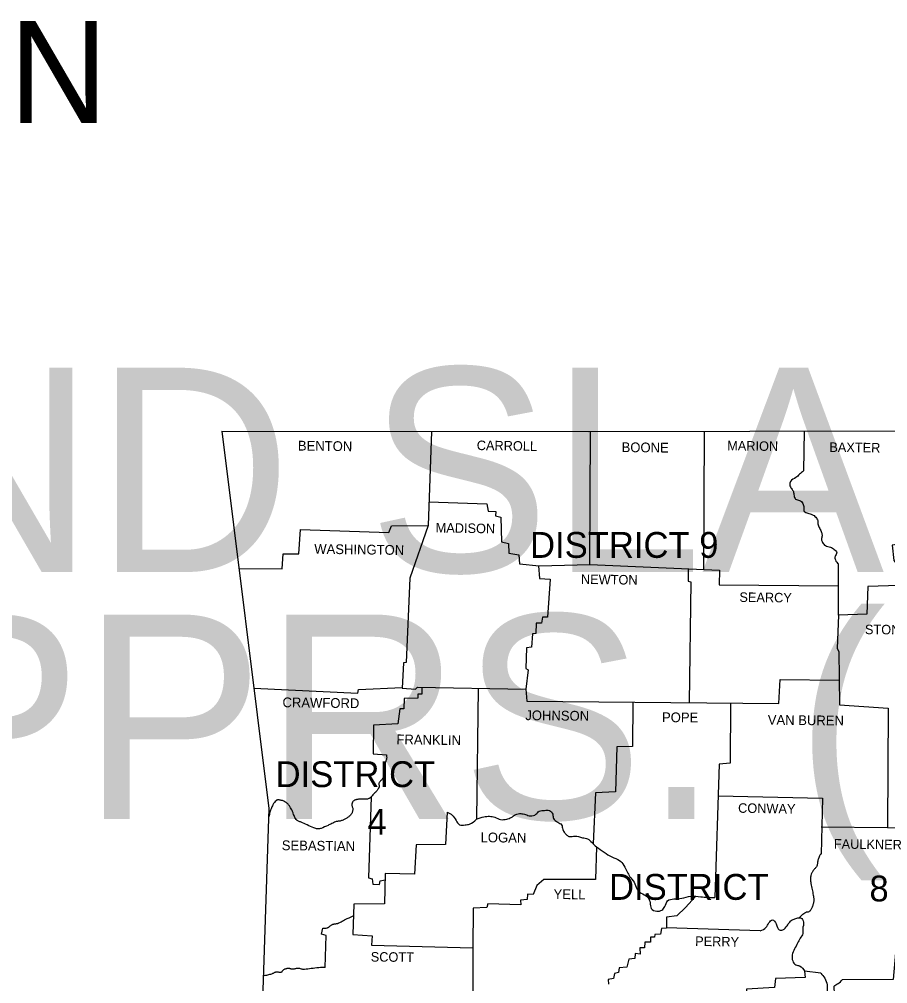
# Model space of a CAD drawing. Extents: x 982240 to 1103002, y 974866 to 1054902.
# Drawn here: x 1073786 to 1087558, y 1039317 to 1054617 of the extents above; entities that cross this region are included whole.
import ezdxf

# ---------------------------------------------------------------- set-up
doc = ezdxf.new("R2010")
doc.units = 0
for name, color, linetype in [('1', 7, 'Continuous'), ('Default', 7, 'Continuous'), ('R_Draft', 7, 'Continuous')]:
    doc.layers.add(name, color=color, linetype=linetype)

msp = doc.modelspace()

# ---------------------------------------------------------------- linework, layer by layer
at = {"layer": '1'}
for points in [[(1076997, 1048082), (1082818, 1048078), (1087927, 1048089), (1093953, 1048183), (1096746, 1048247)], [(1076997, 1048082), (1077743, 1042099), (1077419, 1032332)], [(1087927, 1048089), (1087934, 1047211), (1087873, 1047207), (1087883, 1046311), (1087631, 1046275), (1087653, 1046033), (1087739, 1045922), (1087732, 1045637), (1087243, 1045619), (1087225, 1045180), (1086778, 1045166), (1086757, 1044633), (1086782, 1044590), (1086793, 1043740), (1087563, 1043690), (1087552, 1041793), (1088164, 1041775), (1088164, 1039845), (1087682, 1039809), (1087646, 1039384), (1086836, 1039381)], [(1077269, 1045904), (1077955, 1045900), (1077973, 1046138), (1078221, 1046138), (1078243, 1046523), (1079647, 1046473), (1079690, 1046581), (1080270, 1046584), (1079978, 1045749), (1079920, 1044413), (1079877, 1044410), (1079856, 1044007), (1080068, 1043989), (1080100, 1044021), (1081818, 1043989), (1081836, 1043798)], [(1081836, 1043798), (1085832, 1043765), (1085850, 1044143), (1086788, 1044133)], [(1081062, 1044003), (1081036, 1041926)], [(1080572, 1042041), (1080547, 1041526), (1080079, 1041523), (1080054, 1041055), (1079589, 1041065), (1079575, 1040583), (1079089, 1040579), (1079075, 1040097), (1079380, 1040079), (1079370, 1039931), (1080980, 1039887)], [(1080980, 1039887), (1080975, 1038412), (1080795, 1038409), (1080810, 1038301), (1080637, 1038304), (1080633, 1038225), (1080464, 1038225), (1080468, 1038167), (1080216, 1038160), (1080212, 1037941), (1079967, 1037962), (1079928, 1036191), (1078542, 1036195), (1078509, 1035784), (1078560, 1035748), (1078556, 1035287), (1077518, 1035333)], [(1086498, 1039485), (1086238, 1039514), (1086249, 1039417), (1085778, 1039399), (1085763, 1039258), (1085320, 1039233), (1085295, 1038981), (1085360, 1038949), (1085360, 1038783)]]:
    msp.add_lwpolyline(points, dxfattribs=at)
for points in [[(1080572, 1042041), (1080651, 1041991), (1080712, 1041908), (1080766, 1041839), (1080856, 1041836), (1080928, 1041850), (1081036, 1041926)], [(1086498, 1039485), (1086559, 1039406), (1086595, 1039298), (1086595, 1039175), (1086624, 1039075), (1086681, 1039053), (1086717, 1039139), (1086710, 1039226), (1086710, 1039276), (1086771, 1039319), (1086836, 1039381)]]:
    msp.add_spline(points, degree=3, dxfattribs=at)
at = {"layer": 'Default'}
for points in [[(1080321, 1048080), (1080270, 1046584)], [(1080282, 1046960), (1081198, 1046930), (1081220, 1046815), (1081342, 1046811), (1081339, 1046739), (1081425, 1046717), (1081432, 1046325), (1081544, 1046300), (1081551, 1046145), (1081710, 1046123), (1081717, 1045979), (1082030, 1045947), (1082836, 1045965), (1082844, 1048078)], [(1084647, 1048082), (1084636, 1045889)], [(1086231, 1048085), (1086224, 1047452)], [(1082022, 1045948), (1082037, 1045745), (1082203, 1045735), (1082160, 1045130), (1082084, 1045133), (1082070, 1045036), (1081983, 1045036), (1081980, 1044871), (1081926, 1044867), (1081908, 1044655), (1081828, 1044644), (1081818, 1044320), (1081854, 1044295), (1081818, 1043989)], [(1082836, 1045965), (1084888, 1045879), (1084885, 1045645), (1086776, 1045630)], [(1084395, 1045899), (1084392, 1045702), (1084438, 1045691), (1084409, 1043777)], [(1086778, 1045166), (1086775, 1045976)], [(1077505, 1044004), (1079157, 1043927), (1079165, 1043985), (1079856, 1044018)], [(1080172, 1044020), (1080172, 1043909), (1080104, 1043909), (1080108, 1043845), (1079888, 1043841), (1079884, 1043679), (1079823, 1043679), (1079791, 1043438), (1079402, 1043420), (1079398, 1042963), (1079607, 1042948)], [(1083514, 1043784), (1083511, 1043079), (1083262, 1043075), (1083241, 1042359), (1082924, 1042348), (1082885, 1041540)], [(1085065, 1043772), (1085058, 1042815), (1084885, 1042801), (1084816, 1040684)], [(1079364, 1042281), (1079326, 1040997), (1079380, 1040983), (1079391, 1040896), (1079499, 1040889), (1079510, 1040950), (1079586, 1040963)], [(1084869, 1042300), (1086523, 1042261), (1086501, 1041371)], [(1086505, 1041807), (1087552, 1041793)], [(1082937, 1041490), (1082923, 1040972), (1082102, 1040968), (1081994, 1040875), (1081933, 1040731), (1081843, 1040738), (1081839, 1040655), (1081735, 1040644), (1081738, 1040569), (1081216, 1040583), (1081198, 1040525), (1080982, 1040518), (1080980, 1039887)], [(1084512, 1040703), (1084352, 1040529), (1084212, 1040396), (1084050, 1040371), (1084050, 1040201), (1083970, 1040191), (1083956, 1040104), (1083866, 1040097), (1083859, 1040057), (1083798, 1040054), (1083794, 1039978), (1083708, 1039975), (1083700, 1039888), (1083628, 1039888), (1083632, 1039787), (1083553, 1039795), (1083549, 1039715), (1083452, 1039708), (1083423, 1039579), (1083301, 1039568), (1083290, 1039496), (1083225, 1039478), (1083207, 1039402), (1083124, 1039384), (1083132, 1039309)], [(1078639, 1039575), (1078650, 1040083), (1078578, 1040104), (1078599, 1040201)], [(1085536, 1040158), (1084050, 1040205)]]:
    msp.add_lwpolyline(points, dxfattribs=at)
for points in [[(1086224, 1047452), (1086159, 1047398), (1086102, 1047347), (1086015, 1047286), (1086004, 1047229), (1086033, 1047171), (1086062, 1047124), (1086073, 1047059), (1086098, 1047005), (1086159, 1046984), (1086210, 1046937), (1086228, 1046872), (1086235, 1046811), (1086292, 1046782), (1086357, 1046761), (1086418, 1046717), (1086447, 1046663), (1086454, 1046595), (1086480, 1046541), (1086508, 1046476), (1086516, 1046422), (1086508, 1046368), (1086523, 1046318), (1086570, 1046267), (1086652, 1046242), (1086710, 1046206), (1086750, 1046156), (1086724, 1046095), (1086728, 1046041), (1086775, 1045976)], [(1079607, 1042948), (1079611, 1042929), (1079612, 1042910), (1079607, 1042873), (1079601, 1042853), (1079593, 1042833), (1079585, 1042813), (1079578, 1042793), (1079560, 1042725), (1079561, 1042703), (1079566, 1042680), (1079571, 1042657), (1079572, 1042646), (1079571, 1042635), (1079558, 1042598), (1079539, 1042563), (1079528, 1042548), (1079515, 1042534), (1079502, 1042520), (1079492, 1042505), (1079489, 1042488), (1079492, 1042469), (1079495, 1042451), (1079492, 1042433), (1079486, 1042423), (1079480, 1042413), (1079468, 1042394), (1079454, 1042375), (1079438, 1042358), (1079380, 1042300), (1079358, 1042274), (1079345, 1042262), (1079338, 1042257), (1079334, 1042255), (1079330, 1042253), (1079308, 1042247), (1079285, 1042246), (1079263, 1042246), (1079251, 1042247), (1079240, 1042246), (1079202, 1042244), (1079165, 1042243), (1079145, 1042241), (1079126, 1042237), (1079107, 1042229), (1079098, 1042224), (1079089, 1042217), (1079077, 1042206), (1079069, 1042192), (1079063, 1042178), (1079060, 1042163), (1079061, 1042143), (1079067, 1042122), (1079073, 1042101), (1079075, 1042081), (1079071, 1042060), (1079066, 1042040), (1079046, 1042001), (1079010, 1041966), (1078970, 1041940), (1078930, 1041918), (1078887, 1041901), (1078866, 1041896), (1078844, 1041894), (1078822, 1041892), (1078801, 1041886), (1078771, 1041872), (1078741, 1041858), (1078712, 1041843), (1078682, 1041829), (1078574, 1041782), (1078546, 1041775), (1078516, 1041775), (1078487, 1041780), (1078459, 1041789), (1078351, 1041836), (1078254, 1041879), (1078234, 1041887), (1078213, 1041896), (1078195, 1041907), (1078186, 1041914), (1078182, 1041918), (1078178, 1041922), (1078158, 1041953), (1078143, 1041987), (1078131, 1042022), (1078125, 1042039), (1078117, 1042055), (1078098, 1042092), (1078077, 1042127), (1078063, 1042148), (1078048, 1042166), (1078030, 1042183), (1078020, 1042192), (1078009, 1042199), (1077989, 1042211), (1077968, 1042219), (1077947, 1042224), (1077926, 1042228), (1077909, 1042232), (1077891, 1042234), (1077873, 1042231), (1077865, 1042227), (1077861, 1042224), (1077858, 1042221), (1077809, 1042157), (1077778, 1042090), (1077756, 1042021), (1077738, 1041951)], [(1081036, 1041926), (1081155, 1041965), (1081242, 1041973), (1081328, 1041958), (1081418, 1041922), (1081515, 1041929), (1081587, 1041955), (1081659, 1042001), (1081738, 1042016), (1081814, 1042001), (1081893, 1041980), (1081980, 1042005), (1082030, 1042052), (1082116, 1042066), (1082192, 1042066), (1082246, 1042005), (1082257, 1041940), (1082325, 1041879), (1082386, 1041839), (1082404, 1041764), (1082437, 1041710), (1082469, 1041674), (1082516, 1041652), (1082595, 1041659), (1082718, 1041634), (1082797, 1041616), (1082869, 1041555), (1082937, 1041490)], [(1082937, 1041490), (1083063, 1041404), (1083182, 1041328), (1083304, 1041274), (1083373, 1041195), (1083434, 1041073), (1083484, 1040997), (1083549, 1040903), (1083596, 1040799), (1083672, 1040741), (1083751, 1040691), (1083790, 1040601), (1083808, 1040511), (1083895, 1040468), (1083978, 1040486), (1084024, 1040540), (1084068, 1040633), (1084165, 1040662), (1084291, 1040673), (1084435, 1040705), (1084593, 1040698), (1084816, 1040684)], [(1086501, 1041371), (1086496, 1041373), (1086490, 1041368), (1086478, 1041346), (1086466, 1041316), (1086460, 1041302), (1086454, 1041289), (1086447, 1041261), (1086444, 1041233), (1086441, 1041206), (1086438, 1041193), (1086433, 1041181), (1086420, 1041162), (1086405, 1041146), (1086389, 1041130), (1086375, 1041112), (1086364, 1041093), (1086354, 1041074), (1086339, 1041033), (1086336, 1041020), (1086334, 1041007), (1086332, 1040981), (1086332, 1040955), (1086336, 1040929), (1086354, 1040835), (1086372, 1040745), (1086379, 1040704), (1086383, 1040683), (1086386, 1040662), (1086387, 1040636), (1086383, 1040610), (1086376, 1040584), (1086372, 1040571), (1086368, 1040558), (1086360, 1040533), (1086350, 1040510), (1086338, 1040488), (1086330, 1040478), (1086326, 1040473), (1086321, 1040468), (1086305, 1040458), (1086286, 1040453), (1086266, 1040450), (1086249, 1040443), (1086237, 1040434), (1086225, 1040426), (1086202, 1040408), (1086180, 1040388), (1086161, 1040366)], [(1078599, 1040201), (1078619, 1040199), (1078639, 1040199), (1078669, 1040205), (1078674, 1040207), (1078679, 1040209), (1078689, 1040214), (1078698, 1040220), (1078716, 1040234), (1078734, 1040248), (1078749, 1040257), (1078754, 1040259), (1078766, 1040263), (1078779, 1040265), (1078805, 1040269), (1078831, 1040273), (1078843, 1040276), (1078855, 1040281), (1078880, 1040294), (1078905, 1040308), (1078930, 1040322), (1078956, 1040335), (1079083, 1040393)], [(1085536, 1040158), (1085626, 1040209), (1085673, 1040284), (1085731, 1040331), (1085788, 1040266), (1085839, 1040173), (1085893, 1040173), (1085961, 1040237), (1086004, 1040295), (1086058, 1040338), (1086116, 1040356), (1086177, 1040363), (1086224, 1040295), (1086210, 1040187), (1086210, 1040115), (1086170, 1040039), (1086127, 1039960), (1086080, 1039870), (1086044, 1039773), (1086051, 1039679), (1086102, 1039618), (1086159, 1039600), (1086246, 1039513)], [(1078639, 1039575), (1078613, 1039575), (1078587, 1039575), (1078535, 1039571), (1078416, 1039557), (1078308, 1039543), (1078296, 1039542), (1078283, 1039544), (1078259, 1039550), (1078235, 1039557), (1078217, 1039560), (1078211, 1039561), (1078188, 1039559), (1078165, 1039554), (1078143, 1039549), (1078121, 1039546), (1078105, 1039548), (1078090, 1039553), (1078075, 1039558), (1078059, 1039561), (1078040, 1039560), (1078022, 1039556), (1078003, 1039550), (1077984, 1039543), (1077971, 1039533), (1077962, 1039520), (1077952, 1039508), (1077941, 1039499), (1077930, 1039497), (1077919, 1039497), (1077896, 1039499), (1077872, 1039502), (1077856, 1039501), (1077851, 1039499), (1077834, 1039493), (1077819, 1039485), (1077802, 1039477), (1077786, 1039471), (1077753, 1039461), (1077720, 1039453), (1077688, 1039446), (1077654, 1039441)]]:
    msp.add_spline(points, degree=3, dxfattribs=at)

# ---------------------------------------------------------------- texts
for s, height, rotation, p in [('BENTON', 154.8, 359.2527, (1078203, 1047776)), ('CARROLL', 151.2, 359.1481, (1081040, 1047783)), ('BOONE', 154.8, 359.4001, (1083337, 1047751)), ('MARION', 151.2, 359.1854, (1085011, 1047779)), ('BAXTER', 151.2, 359.2559, (1086631, 1047754)), ('MADISON', 151.2, 359.0906, (1080388, 1046476)), ('WASHINGTON', 154.8, 359.232, (1078463, 1046138)), ('NEWTON', 151.2, 359.2717, (1082692, 1045659)), ('SEARCY', 151.2, 359.2527, (1085205, 1045375)), ('STONE', 151.2, 359.4001, (1087196, 1044863)), ('CRAWFORD', 154.8, 359.277, (1077959, 1043704)), ('JOHNSON', 154.8, 359.3514, (1081810, 1043499)), ('POPE', 154.8, 359.6155, (1083978, 1043467)), ('VAN BUREN', 154.8, 359.3508, (1085655, 1043427)), ('FRANKLIN', 154.8, 359.1815, (1079766, 1043117)), ('CONWAY', 151.2, 359.0371, (1085184, 1042030)), ('LOGAN', 154.8, 359.3969, (1081101, 1041562)), ('SEBASTIAN', 154.8, 359.2816, (1077948, 1041436)), ('FAULKNER', 151.2, 359.2486, (1086703, 1041461)), ('YELL', 154.8, 359.1987, (1082257, 1040662)), ('PERRY', 151.2, 359.0858, (1084503, 1039917)), ('SCOTT', 151.2, 359.4063, (1079359, 1039669))]:
    msp.add_text(s, height=height, rotation=rotation, dxfattribs=at).set_placement(p)
for s, height, p in [('DISTRICT 9', 410.4, (1081886, 1046073)), ('DISTRICT', 410.4, (1077851, 1042436)), ('4', 410, (1079309, 1041680)), ('DISTRICT', 410.4, (1083139, 1040648)), ('8', 410, (1087268, 1040623))]:
    msp.add_text(s, height=height, dxfattribs=at).set_placement(p)
at = {"layer": 'R_Draft'}
for s, height, p in [('ARKANSAS DEPARTMENT OF TRANSPORTATION ', 1620, (1023676, 1052972)), ('LA GRUE BAYOU, WOLF ISLAND SLASH', 3240, (1010938, 1045849)), (' & HONEY CREEK STRS. & APPRS. (S)', 3240, (1012901, 1041933))]:
    msp.add_text(s, height=height, dxfattribs=at).set_placement(p)

doc.saveas('drawing.dxf')
